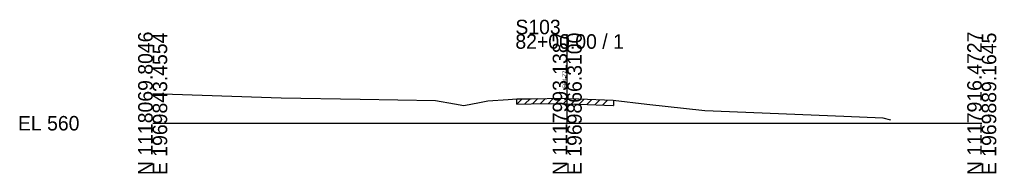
# Model space of a CAD drawing. Extents: x -26 to 163, y -10 to 45020.
# Drawn here: x -25.7 to 162.8, y 40990.3 to 41020 of the extents above; entities that cross this region are included whole.
import ezdxf

# ---------------------------------------------------------------- set-up
doc = ezdxf.new("R2010")
doc.units = 0
for name, color, linetype in [('RD_GPK_XS_Cell', 7, 'Continuous'), ('RD_XS_ExGround', 7, 'Continuous'), ('RD_XS_ExPaveRet', 7, 'Continuous'), ('RD_XS_TX_Elev_EX', 7, 'Continuous')]:
    doc.layers.add(name, color=color, linetype=linetype)

msp = doc.modelspace()

# ---------------------------------------------------------------- linework, layer by layer
at = {"layer": 'RD_GPK_XS_Cell'}
for p, q in [((80, 41000), (80, 41017.17)), ((0, 41000), (80, 41000)), ((80, 41000), (160, 41000))]:
    msp.add_line(p, q, dxfattribs=at)
at = {"layer": 'RD_XS_ExGround'}
for p, q in [((0, 41005.72), (24.8, 41004.91)), ((24.8, 41004.91), (40.07, 41004.65)), ((40.07, 41004.65), (54.6, 41004.38)), ((54.6, 41004.38), (58.25, 41003.75)), ((60.06, 41003.44), (63.08, 41004.03)), ((63.08, 41004.03), (64.66, 41004.34)), ((64.66, 41004.34), (68.62, 41004.6)), ((68.62, 41004.6), (70.3, 41004.69)), ((70.3, 41004.69), (73.06, 41004.74)), ((73.06, 41004.74), (79.13, 41004.81)), ((79.13, 41004.81), (80, 41004.77)), ((80, 41004.77), (82.25, 41004.68)), ((82.25, 41004.68), (88.88, 41004.43)), ((88.88, 41004.43), (95.39, 41003.69)), ((58.25, 41003.75), (60.06, 41003.44)), ((95.39, 41003.69), (106.55, 41002.45)), ((106.55, 41002.45), (133.4, 41001.39)), ((133.4, 41001.39), (140.92, 41001.03)), ((140.92, 41001.03), (142.41, 41000.66))]:
    msp.add_line(p, q, dxfattribs=at)
at = {"layer": 'RD_XS_ExPaveRet'}
for p, q in [((70.3, 41003.69), (71.32, 41004.71)), ((70.3, 41003.69), (70.3, 41004.69)), ((71.8, 41003.72), (72.82, 41004.73)), ((73.3, 41003.74), (74.31, 41004.75)), ((74.8, 41003.76), (75.81, 41004.77)), ((76.3, 41003.77), (77.31, 41004.79)), ((77.8, 41003.79), (78.81, 41004.8)), ((79.3, 41003.8), (80.26, 41004.76)), ((80.8, 41003.74), (81.76, 41004.7)), ((82.3, 41003.68), (83.27, 41004.64)), ((83.8, 41003.62), (84.77, 41004.58)), ((85.3, 41003.56), (86.27, 41004.53)), ((86.8, 41003.51), (87.77, 41004.47)), ((88.92, 41004.43), (88.92, 41003.43)), ((70.3, 41003.69), (73.06, 41003.74)), ((73.06, 41003.74), (79.13, 41003.81)), ((79.13, 41003.81), (80, 41003.77)), ((80, 41003.77), (82.25, 41003.68)), ((82.25, 41003.68), (88.88, 41003.43)), ((88.88, 41003.43), (88.92, 41003.43))]:
    msp.add_line(p, q, dxfattribs=at)

# ---------------------------------------------------------------- texts
at = {"layer": 'RD_GPK_XS_Cell'}
for s, p in [('S103', (70, 41017.17)), ('82+00.00 / 1', (70, 41014.37)), ('EL 560', (-26, 40998.6))]:
    msp.add_text(s, height=2.8, dxfattribs=at).set_placement(p)
for s, p in [('N 1118069.8046', (0, 40990)), ('E 1969843.4554', (2.8, 40990)), ('N 1117993.1387', (80, 40990)), ('E 1969866.3100', (82.8, 40990)), ('N 1117916.4727', (160, 40990)), ('E 1969889.1645', (162.8, 40990))]:
    msp.add_text(s, height=2.8, rotation=90, dxfattribs=at).set_placement(p)
at = {"layer": 'RD_XS_TX_Elev_EX'}
msp.add_text('564.77', height=0.8, rotation=90, dxfattribs=at).set_placement((79.9, 41006.77))

doc.saveas('drawing.dxf')
